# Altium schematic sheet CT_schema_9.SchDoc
size 274 x 160 mm
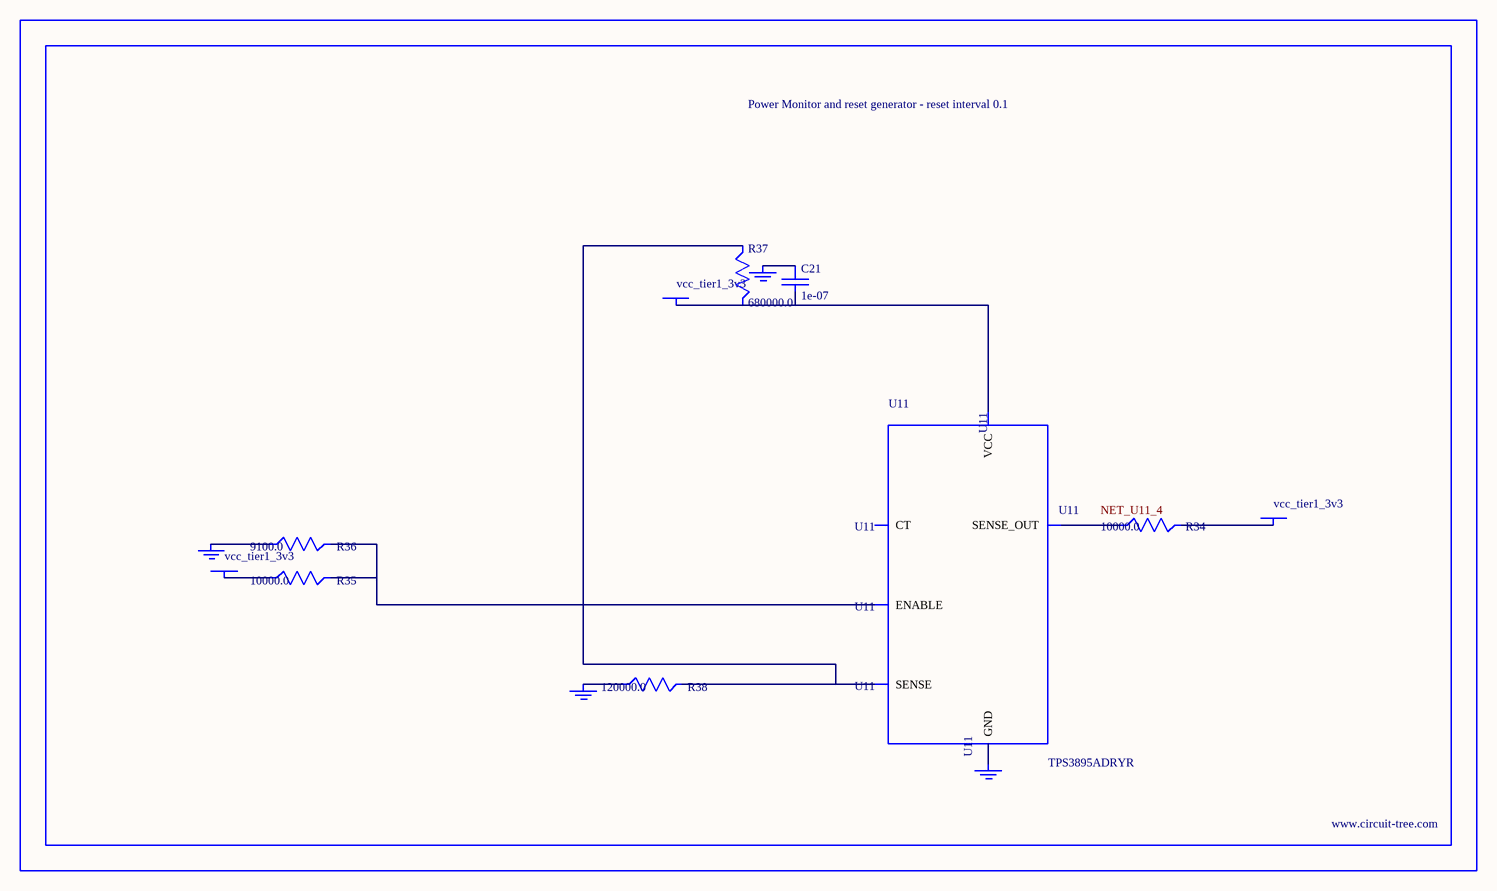
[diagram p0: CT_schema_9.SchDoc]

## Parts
BORDER8  (no value)
C21  1e-07  [C0402]
GND_INSTANCE_8_0  (no value)
GND_INSTANCE_8_1  (no value)
GND_INSTANCE_8_2  (no value)
GND_INSTANCE_8_3  (no value)
POWER_INSTANCE_8_0  vcc_tier1_3v3
POWER_INSTANCE_8_1  vcc_tier1_3v3
POWER_INSTANCE_8_2  vcc_tier1_3v3
R34  10000.0  [R0603]
R35  10000.0  [R0603]
R36  9100.0  [R0603]
R37  680000.0  [R0603]
R38  120000.0  [R0603]
U11  TPS3895ADRYR  [SON-6]

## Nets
NetC21_1: C21.1 GND_INSTANCE_8_2.0(GND)
NetC21_2: C21.2 POWER_INSTANCE_8_2.0(PWR) R37.2 U11.6(VCC)
NetGND_INSTANCE_8_0_0: GND_INSTANCE_8_0.0(GND) R36.1
NetGND_INSTANCE_8_1_0: GND_INSTANCE_8_1.0(GND) R38.1
NetGND_INSTANCE_8_3_0: GND_INSTANCE_8_3.0(GND) U11.2(GND)
NetPOWER_INSTANCE_8_0_0: POWER_INSTANCE_8_0.0(PWR) R35.1
NetPOWER_INSTANCE_8_1_0: POWER_INSTANCE_8_1.0(PWR) R34.2
NetR34_1: R34.1 U11.4(SENSE_OUT)
NetR35_2: R35.2 R36.2 U11.1(ENABLE)
NetR37_1: R37.1 R38.2 U11.3(SENSE)

Not connected (* = marked no-connect by the designer): U11 5(CT)

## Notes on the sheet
- Labels drawn without touching a wire or pin: NET_U11_4

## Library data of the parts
BORDER8 = BORDER_PAGE8
C21 = C0402C104K3RACTU
GND_INSTANCE_8_0-GND_INSTANCE_8_3 = GND
POWER_INSTANCE_8_0-POWER_INSTANCE_8_2 = PWR
R34 R35 = RC0603JR-0710KL
R36 = RC0603JR-079K1L
R37 = RC0603JR-07680KL
R38 = RC0603JR-07120KL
